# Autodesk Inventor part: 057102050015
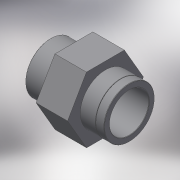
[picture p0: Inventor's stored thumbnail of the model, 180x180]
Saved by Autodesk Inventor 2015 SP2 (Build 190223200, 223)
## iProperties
Created: 2017-10
Part Number: 057102050015
Material: Generic
Description: PLASSON AD. SOCKET REINF.PVC 50-1.1/2"
Document SubType Name: Modeling
Designer: KIM
Density: 1 g/cm^3
Appearance: Default
Author: KIM
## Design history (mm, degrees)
derived "057102.ipt"
feature "Solid1::057102.ipt"
tag "TaggingFeature1"
body "Solid1"
other parameters: "d0" = 57, "d2" = 63, "d3" = 44.845, "d5" = 31, "d6" = 22, "d8" = 57.5, "d10" = 15.4, "d13" = 0, "d14" = 0.5, "d15" = 16, "d16" = 5.5, "d18" = 0.1, "G_" = 44.845, "C_" = 63, "B_" = 16, "l_" = 31, "lt_" = 22, "H_" = 57
